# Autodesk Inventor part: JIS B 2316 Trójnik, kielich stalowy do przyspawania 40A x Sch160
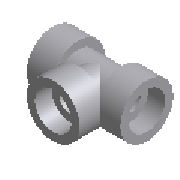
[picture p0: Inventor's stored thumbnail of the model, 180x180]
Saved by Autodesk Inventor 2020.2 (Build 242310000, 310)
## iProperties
Manager: www.cadconsulting.pl
Company: Fabian Stasiak CAD Consulting
Created: 2014-02
Part Number: JIS B 2316 Trójnik, kielich stalowy do przyspawania 40A x Sch160
Material: Stal
Description: Trójnik
Document SubType Name: Modeling
Standard: JIS B 2316
Designer: F.Stasiak
Standards Organization: JIS
Language: pl-PL
Size Designation: 40A x Sch160
Categories: <MemberInstance><Categories><Category DisplayName="Rury cienko- i grubościenne" InternalName="4347fa0f-2144-441d-94cd-e3e15c92b736" Mnemonic="TUBEANDPIPE"><Cate
Density: 1 g/cm^3
Appearance: Płyta
Catalog Web Link: www.expertbooks.pl
NAME: PIPING: JIS B 2316 Steel Socket Welding Tee
DATA: <meta><inlinegroups number="1" deflen="6.98"></inlinegroups><connections number="3"></connections><angles><a>3.14159265358979</a><a>1.57079632679489</a></angles
IsCustomPart: 0
Author: F.Stasiak
Subject: Zbiór ćwiczeń. Autodesk Inventor 2020. Kurs Professional
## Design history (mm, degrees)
sketch "Sketch1"
  geometry: L1 (0, 0)-(50.8, 0); L2 (50.8, 0)-(50.8, 25); L3 (20.5, 32.35)-(0, 32.35); L4 (0, 24.55)-(0, 0); L5 (12.7, 24.55)-(12.7, 17.2); L6 (12.7, 17.2)-(50.8, 17.2); L7 (20.5, 32.35)-(20.5, 25); L8 (20.5, 25)-(50.8, 25); L9 (0, 24.55)-(0, 32.35); L10 (88.9, 17.2)-(50.8, 17.2); L11 (101.6, 24.55)-(101.6, 32.35); L12 (81.1, 32.35)-(101.6, 32.35); L13 (81.1, 32.35)-(81.1, 25); L14 (81.1, 25)-(50.8, 25); L15 (101.6, 24.55)-(101.6, 0); L16 (101.6, 0)-(50.8, 0); L17 (0, 24.55)-(12.7, 24.55); L18 (101.6, 24.55)-(88.9, 24.55); L19 (88.9, 24.55)-(88.9, 17.2); L20 (0, 24.55)-(0, 0); L21 (0, 0)-(101.6, 0); L22 (101.6, 0)-(101.6, 24.55); C1 r 3.9 at (16.6, 28.45); C2 r 3.9 at (16.6, 21.1)
  constraints: 44 end point, 7 symmetric about line, 7 tangent, 5 perpendicular, 4 parallel, 2 centre point, 2 horizontal, 1 collinear, 1 equal radius, 1 point on line, 9 other
  dimensions: "d0" = 34.4 diameter of L6 L1 (= D); "d1" = 12.7 distance between parallel lines of L9 L5 (= C1); "d2" = 38.1 distance between parallel lines of L2 L5 (= G); "d6" = 49.1 diameter of L4.start L1 (= S); "d7" = 7.8 distance of L4.start L3.end (= T)
revolve "Revolve1" stored, may be unused: angle "d8" = 90 deg
sketch "Sketch2"
  geometry: L1 (0, 0)-(-50.8, 0) reference; L2 (-50.8, 0)-(-50.8, 50.8); L3 (-50.8, 50.8)-(-75.35, 50.8); L4 (-83.15, 50.8)-(-83.15, 30.3); L5 (-68, 0)-(-50.8, 0); L6 (-75.35, 38.1)-(-68, 38.1); L7 (-68, 38.1)-(-68, 0); L8 (-75.35, 50.8)-(-83.15, 50.8); L9 (-83.15, 30.3)-(-75.8, 30.3); L10 (-75.8, 30.3)-(-75.8, 0); L11 (-68, 0)-(-75.8, 0); L12 (-75.35, 50.8)-(-75.35, 38.1); L13 (-75.35, 50.8)-(-50.8, 50.8); L14 (-50.8, 50.8)-(-50.8, 0); L15 (-50.8, 0)-(-68, 0); C1 r 3.9 at (-79.25, 34.2); C2 r 3.9 at (-71.9, 34.2)
  constraints: 28 end point, 8 tangent, 6 perpendicular, 2 centre point, 2 parallel, 1 vertical
  dimensions: "d3" = 34.4 diameter of L7 L2 (= D); "d4" = 12.7 distance between parallel lines of L6 L8 (= C1); "d5" = 38.1 distance between parallel lines of L6 L5 (= G); "d9" = 49.1 diameter of L3.end L2 (= S); "d10" = 7.8 distance of L3.end L4.start (= T)
revolve "Revolve2" stored, may be unused: angle "d18" = 90 deg
revolve "Revolve3" stored, may be unused: angle "d57" = 90 deg
revolve "Revolve4" stored, may be unused: angle "d58" = 90 deg
workaxis "Work Axis1"
workaxis "Work Axis3"
workpoint "Work Point2"
workpoint "Work Point3"
workaxis "Work Axis4"
workpoint "Work Point4"
workpoint "Work Point5"
workaxis "Work Axis5"
workpoint "Work Point6"
workpoint "Work Point7"
body "Solid1"
other parameters: "S" = 49.1 [user parameter; used in 2 equation terms], "D" = 34.4 [user parameter; used in 2 equation terms], "T" = 7.8 [user parameter; used in 2 equation terms], "C1" = 12.7 [user parameter; used in 2 equation terms], "G" = 38.1 [user parameter; used in 2 equation terms], "Size_Designation" = 12.345 [user parameter]
